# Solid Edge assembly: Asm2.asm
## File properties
Author: Sarvanan
Template: sync ansi assembly.asm
Last saved by: CADCIM
Revision: 22
Application: Solid Edge
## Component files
end plate.par
disk.par
support pin.par
spacer.par
center pin.par
bolt.par
nut.par
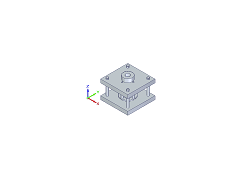
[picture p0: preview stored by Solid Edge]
